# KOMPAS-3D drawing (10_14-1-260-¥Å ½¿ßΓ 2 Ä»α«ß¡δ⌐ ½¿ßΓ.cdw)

Views: Вид транспорта
Referenced files in D:\ТИ-064\: Опр. лист.cdw
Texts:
  Текст на чертеже
  Размерные надписи
  Шероховатость
  Линия выноски #1
  Линия выноски #2
  Линия выноски #3
  Отклонения формы и база
  Заголовок таблицы
  Ячейка таблицы
  Стрелка вида
  Обозначение изменения
  Фигурная скобка
  Номер узла
  Марка координационной оси
  VRCB
  Выносная надпись
  Обозначение узла
  Марка/позиционное обозначение с линией-выноской
  Марка/позиционное обозначение на линии
  Марка/позиционное обозначение без линии-выноски
  Лит-Масса-Масштаб
  Материал-Предприятие
  Normal
  Body Text
  Title Specification
  Body Specification ( left align )
  Body Specificaton ( centered )
  Title
  Без имени
  Additional DXF text style 0
  heading 1
  Знак Знак Знак Знак Знак Знак
  Verdana
  Simplex
  Txt
  MS Sans Serif
  Обычный
  Термин
  Список определений
  Адрес
  Цитаты
  Форматированный
  Courier New
  Z-конец формы
  Z-начало формы
  txt
  ТекстШаг1
  Денис
  TXT
  heading 8
  heading 3
  heading 6
  heading 7
  russ
  ООббыыччнныыйй
  ТТееррммиинн
  ССппииссоокк ооппррееддееллеенниийй
  ААддрреесс
  ЦЦииттааттыы
  ФФооррммааттиирроовваанннныыйй
  Z-ккооннеецц ффооррммыы
  Z-ннааччааллоо ффооррммыы
  Абзац Знак
  heading 2
  heading 4
  heading 5
  heading 9
  GOST 2.304 type A
  rustxt
  цепи
  ссылки
  Маркировка
  style2
  Definition Term
  Definition List
  Address
  Blockquote
  Preformatted
  z-Bottom of Form
  z-Top of Form
  header
  AGOpus
  footer
  Body Text 3
  Шрифт 2.5
  Заголовки
  RUSTXT
  NormalParagraphStyle
  Подпись в квадратике
  табл
  клеммы, контакты
  тексты табл
  Тексты. 3,2
  ЗОНА_привяз
  текст переноса
  HeliosLight
  Pa3
  Pa1
  Три с половиной
  маркировка
  ГОСТ_МНЕ
  ESK - Обозначение
  ISOCP
  Table Contents
  Table Heading
  CNBNDG+TimesNewRoman
  Subtitle
  ROMANS
  SIMPLEX
  Heading
  HiddenHorzOCl
  CM2
  CM7
  CM3
  CM4
  CM8
  CM9
  Aioiaue
  Courier New Cyr
  ISOCPEUR
  Текст 3,5
  Tahoma
  Обычный (веб)
  eskd1
  Pa15
  Pa18
  FR5
  romanc
  Аппараты
  подписи
  Состав чартежа
  ячейка табл.
  Ссылки
  Пояснения
  Клеммник текст
  CM12
  romans
  gif
  Пояснения 2
  текст табл
  CC С?т?и?л?ь? П?о? ц?е?н?т?р?у?
  скрытый
  Тип КТПБ(М)
  № чертежа опросного
  листа на
  КРУ
  ОПУ
  Тип разборного ОПУ
  Номинальный ток ввода КРУ 10(6)кВ,           -
  Тип разъединителя
  Тип выключателя
  Тип трансформатора тока
  Тип трансформатора напряжения
  Тип аппарата защиты от
  перенапряжений
  Тип аппарата защиты нейтрали обмоток ВН силового
  трансформатора
  Блок приема ВЛ 110 кВ
  МП-1
  МП-2
  МП-1, МП-2
  МЛ-1, МЛ-2
  МЛ-1
  МЛ-2
  Заглубленное
  Молниеотводы, шт.,
  устанавливаемые на
  ж/б опорах ВЛ 35 и 110 кВ
  ж/б стойках типа СК
  ж/б опорах ВЛ220 кВ  (железобетонных стойках типа СК)
  металлических опорах ВЛ-220 кВ
  порталах 220, 110, 10(6) кВ
  ж/б стойках типа ВС 220, 110, 10(6) кВ
  Внешнее ограждение подстанции, п. м.
  Незаглубленное
  Элементы портала
  Кронштейны, устанавливаемые на
  концевой опоре ВЛ
  Шумозащитное ограждение, п.м.
  Технические
  характеристики
  блоков 35 кВ
  Назначение блоков 35(20) кВ
  Тип блока
  Схема вспомогательных соединений блока
  Коэффициент трансформации
  трансформаторов тока 35 кВ
  Исполнение привода выключателя
  ОГК.365
  выносных
  встроенных
  РТМ
  ТЭО
  Ток катушки РТМ привода КЗ 110 кВ, Io, А
  Схема вспомогательных соединений блока КЗ 110 кВ
  Ток катушки РТМ привода КЗ 220 кВ,   0, А
  Схема и количество щитков сигнализации на дому
  Количество обрабатываемых фаз
  ВЧ связи (ВЧ-оборудование не входит
  в поставку завода)
  Модуль ОРУ 110 кВ
  Номинальный ток ячейки,А
  Ток термической стойкости,кА
  ОРУ 110 кВ
  по развитым
  схемам
  Номинальный ток сборных шин, _______А, количество трехфазных пролетов __________шт
  ОРУ 220 кВ
  Тип блока 110(220) кВ
  Схема вспомогательных соединений блока 110(220) кВ
  Тип привода разъединителя 35 кВ
  Тип привода разъединителя 110(220) кВ
  Модуль ОРУ220 кВ
  Номинальный ток ячейки, А
  Ток термической стойкости, кА
  Номинальный ток сборных шин, ______А, количество трехфазных пролетов_________шт
  Б 110-62-Б-ХЛ1 (2 шт.)
  Таблица 2.
  Заполняется заводом
  № договора
  Согласовал
  Подпись
  Дата
  Заказчик, адрес, индекс             Согласовано
  Руководитель предприятия
  Подпись, дата
  Таблица 1. Заполняется проектной организацией
  Заказчик и его адрес
  Согласовано
  Филиал ОАО "Тюменьэнерго" - "Северные электрические сети"
  ЯНАО, г. Новый Уренгой, Северо-восточная промзона
  Фамилия                  Подпись
  Наименование подстанции: КНС-2
  Требования к ПРБМ "Исеть"
  Устанавливаемое оборудование 110 кВ
  Тип
  Завод-изготовитель
  № опросного листа
  аппарат
  привод
  Разъединитель
  SGF-123nII* 100 УХЛ1 +1Е/2МТ-100 УХЛ1
  МТ100
  АВВ
  SGF-123nII* 100 УХЛ1 +2Е/3МТ-100 УХЛ1
  Выключатель
  ВЭБ-110II*-40/2500 УХЛ1
  ППрК
  ЗАО "Энергомаш (Екатеринбург)-Уралэлектротяжмаш"
  Трансформатор тока
  Трансформатор напряжения
  Ограничитель перенапряжений
  Конденсатор связи
  ВЧ заградитель
  Фильтр присоединения
  Разъединитель однофазный
  (для оборудования ВЧ связи)
  нейтрали силового трансформатора
  Заземлитель нейтрали
  силового трансформатора
  Устанавливаемое оборудование  35 кВ
  Климатические условия площадки строительства
  Район по ветру (ПУЭ 7 изд.)
  Район по гололеду (ПУЭ 7 изд.)
  Степень загрязнения атмосферы ГОСТ 9920
  Климатическое исполнение по ГОСТ 15150
  Сейсмичность района (по шкале MSK)
  Температура наиболее холодной пятидневки,  С
  СРВ-123 ХЛ1
  ОПН-110/88-10/900(III) 4УХЛ1
  СМПВ-110/ 3 -6,4 ХЛ1
  ВЗ-630-0,5 ХЛ1
  ФП-6400/48-1000 ХЛ1
  РВО-10/400 ХЛ1
  ОПНН-110/56-10/900(III) 4УХЛ1
  ЗОН-110 M-I УХЛ1
  ВГБЭ-35-12,5/630 УХЛ1
  ВГБЭ-35-12,5/1000 УХЛ1
  РГ.2-35II/1000 УХЛ1
  РГ.1б-35II/1000 УХЛ1
  GEF-40,5 УХЛ1
  ПКН-001-35 ХЛ1
  ОПН-35/40,5-10/650(II) УХЛ1
  РГ.1б-35II/2000 УХЛ1
  РГ.2-35II/2000 УХЛ1
  GEF-12 УХЛ1
  GIF-12 УХЛ1
  ТМГ-160/6 УХЛ1
  ПКТ102-6-40-31,5 У3
  ОПН-6/7,2-10/250(I) УХЛ1
  РМДТУ-01
  ПД-14 УХЛ1
  ПЭМ-4
  ПРГ-5 УХЛ1
  УХЛ1
  ЗАО "Феникс-88"
  ЗАО НПП "Электронные информационные системы"
  ЗАО "ЗЭТО"
  ООО "НИТ-РУСЬ"
  ООО "ТД АВК-Энерго"
  ЗАО "Электрощит"
  Дополнительные требования
  Тип фундаментов (лежни, сваи, иное)
  Высота фундамента (с учетом ростверка), мм
  Разделение кабелей в лотках (1 уровень/2 уровня)
  Требования для жесткой ошиновки
  Ток термической стойкости жесткой ошиновки, кА
  Ток электродинамической стойкости жесткой ошиновки, кА
  Допустимый длительный ток жесткой ошиновки, А
  Цветовая маркировка шин (маркировочные кольца/иное*)
  86/02-19-01-113-ЭП.ЛО6, ЛО7
  сваи
  покрывной слой эмаль Политон УР
  Предохранитель
  Устанавливаемое оборудование 6 кВ
  Шкаф КРУ-СЭЩ-59-14 УХЛ1
  с трансформатором собственных нужд
  Номер типовой схемы: 110-4Н-2/35-9/6 УХЛ1
  Комплектность поставки
  Тип, № опросного листа, примечание
  Портал стальной 110 кВ
  Портал стальной 35 кВ
  Ростверки для порталов
  Наголовники
  см. дополнительные требования п.п. 4
  см. дополнительные требования п.п. 5
  см. дополнительные требования п.п. 6
  см. дополнительные требования п.п. 7
  Площадка обслуживания привода выключателя (Да/Нет)
  Да, площадку выполнить открытого типа
  Ростверки для БМК (Да/Нет)
  Провод для комплекта контактно-натяжной арматуры
  Комплект жесткой ошиновки (Да/Нет)
  Отдельностоящие блоки опорных изоляторов
  Блок опорных изоляторов БО-110-ОИ-52-20
  Блок опорных изоляторов и ОПН БО-110-ОИ/ОПН-57-20
  Блок опорных изоляторов БО-35-ОИ-55-13,5
  Блок опорных изоляторов и ОПН БО-35-ОИ/ОПН-55-13,5
  Блок опорных изоляторов БО-10-ОИ-35-10
  Блок опорных изоляторов БО-10-ОИ-25-7
  Блок опорных изоляторов БО-10-ОИ-30-7
  Блок опорных изоляторов БО-10-ОИ-34,7-7
  Нетиповые блоки
  Блок контроля напряжения 6 кВ БО-35-КН-20-10
  Блок разъединителя и трансформатора тока БО-35-РЗ/ТТ-29-10
  Модуль опорный БМК-10-М1
  ИОС-110-400-УХЛ1
  ИОС-110-400-УХЛ1, ОПН-110/88-10/900(III) 4 УХЛ1
  ИОС-35-500
  ИОС-35-500-01 УХЛ1; ОПН-35/40,5-10/650(II) 4УХЛ1
  ИОС-10-2000 УХЛ1
  ИОС-20-2000 УХЛ1
  ОНШ-10-6 УХЛ1
  86/02-19-01-260-ЭП Лист 22
  86/02-19-01-260-ЭП Лист 23
  86/02-19-01-260-ЭП Лист 24
  Осветительная установка (с комплектом крепления на порталах)
  Факел Р 2х250Ж
  см. дополнительные требования п.п. 12
  Осветительная установка (с комплектом крепления на блоках опорных изоляторов)
  АС 300/48
  для НН
  для СН
  для ВН
  АС 600/72
  АС 150/24
  ПСЛ-110 Я2С
  ПСЛ-110 Я1С
  ПС-35Я4Си
  ПС-35и
  ТС-23 (С)
  Дополнительные требования:
  1. Опросный лист смотреть совместно с планом расположения оборудования см. (10/14-1-113-ЭП л. 2,3).
  2. Включить в поставку 4 пониженных блока Б 10-77/1-П2000 Б-УХЛ1 (см. 10/14-1-260-ЭП л. 3).
  3. На блоках Б 110-62-Б-ХЛ1 предусмотреть возможность установки ограничителей перенапряжений
  ОПНН-110/56-10(II) 4УХЛ1 производства ЗАО "Феникс-88" г. Новосибирск (не входят в поставку
  завода-изготовителя КТП-СЭЩБ(М)).
  4. Выполнить антикоррозийную обработку методом горячего цинкования опор под оборудование.
  Портал ПС-35и индивидуального изготовления из элементов в соответствии с 3.407.2-162
  "Унифицированные стальные порталы открытых распределительных устройств 35-150 кВ для обычных
  и северных районов" выпуск 2 (см. 86/02-19-01-113-КС л. 13);
  Выполнить антикоррозийную обработку методом горячего цинкования порталов, опор под
  оборудование и всех ростверков по ГОСТ 9.307;
  На блоки ОПН 110 кВ установить датчики тока утечки РМДТУ-01 на высоте, доступной для
  подключения к ним измерительного прибора;
  Ящики сварки установить на площадку обслуживания привода выключателя 110 кВ и блок опорных
  изоляторов 35 кВ в соответствии с 86/02-19-01-113-ЭП л. 2;
  Гасящие устройства DE 6 (поставляются комплектно с трансформаторами напряжения) для
  трансформаторов напряжения 6 и 35 кВ разместить в шкафу зажимов трансформаторов напряжения
  (см. 86/02-19-01-260-ЭП л. 21);
  Осветительные установки расположить в соответствии с 86/02-19-01-030-ЭН Лист 3.
  КТП-СЭЩБ(М)-110-5H-Х/10-2х40000-63-А-2-85-УХЛ1
  Дополнительное оборудование:
  1. Комплект гибкой ошиновки 110, 35, 6 кВ.
  2. Комплектно с блоками Б 10-77/1-П2000 Б-УХЛ1 включить в поставку опорый изолятор
  ИОС-10-2000 УХЛ1 производства ООО "ВТФ Электрофарфор" г. Москва в количестве 12 шт.
  3. Включить в поставку шкаф зажимов трансформатора напряжения 110 кВ согласно опросному листу
  (см. 10/14-1-051-ЭП.ОЛ3).
  4. Комплектно с блоками Б 110-62-Б-ХЛ1 включить в поставку 2 заземлителя нейтрали ЗОН
  СЭЩ-110/IIУХЛ1 (см. 10/14-1-113-ЭП.ОЛ3).
  ГИП
  Маленкин
  Н.контр.
  Опросный лист
  на КТП-СЭЩБ(М)-110кВ
  Реконструкция ПС 110 кВ Опорная
  (замена трансформаторов 16МВА на 40МВА)
  на КТП СЭЩБ(М)-110
  Разраб.
  Скахин
  Опросный лист на КТП-Б(М)
Dimensions and other numbers on the sheet: 10/14-1-260-ЭП; 7; 3.5; 2.5; 2,5; 1,8; 2.5 курсив; 2,5_3; 3,2 (надписи); 3,5_01; 2,5_01; 3,5_tabl; 5_заголовок; 2,3_; 3,2_; 3,2_зона не привяз; 2,5 грязносинь; 2,5 (контакты, клеммы); 3,2; 3,2 (Зоны); 5; 3,5; 3.2 маркировка; 3,2 элементы; 3,2 линия; 3,2 таблица; 2.5_Э5_надписи; 2.5_Э5_ссылки; 2.5_кабель; 3.2; 2.5 надписи; 3 и 5; 5,0_белый_подчёркнутый; 3.2 фиол; 3.2 (текст); 1; 2; 3; 4; 8; 35 кВ; 9; 110 кВ; 10; 220 кВ; 11; 12; 13; 14; 15; 16; 17; 18; 19; 20; 21; 23; 24; 25; 26; 27; 28; 29; 30; 31; 32; 33; 34; 35; 36; 37; 38; 39; 6; 22; 40; 41; 42; 43; 44; 45; 46; 47; 48; 49; 50; 51; 52; 53; 54; 55; 56; 57; 58; 59; 60; 62; 63; 86/02-19-01-113-ЭП.ЛО5; 86/02-19-01-113-ЭП.ЛО1; -43; 86/02-19-01-113-ЭП.ЛО4; 86/02-19-01-113-ЭП.ЛО2; 86/02-19-01-113-ЭП.ЛО3; 86/02-19-01-113-ЭП.ЛО8; 86/02-19-01-113-ЭП.ЛО9; 86/02-19-01-113-ЭП.ЛО10; 86/02-19-01-113-ЭП.ЛО11; 86/02-19-01-113-ЭП.ЛО12; 650; 2 уровня; 125; 2000; 31,5; 80; 1000; 120 м.; 200 м.; 270 м.; 23-2006-ЭП.1; 11.12; 11.09/86.009-Т5.1-ЛО.7-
